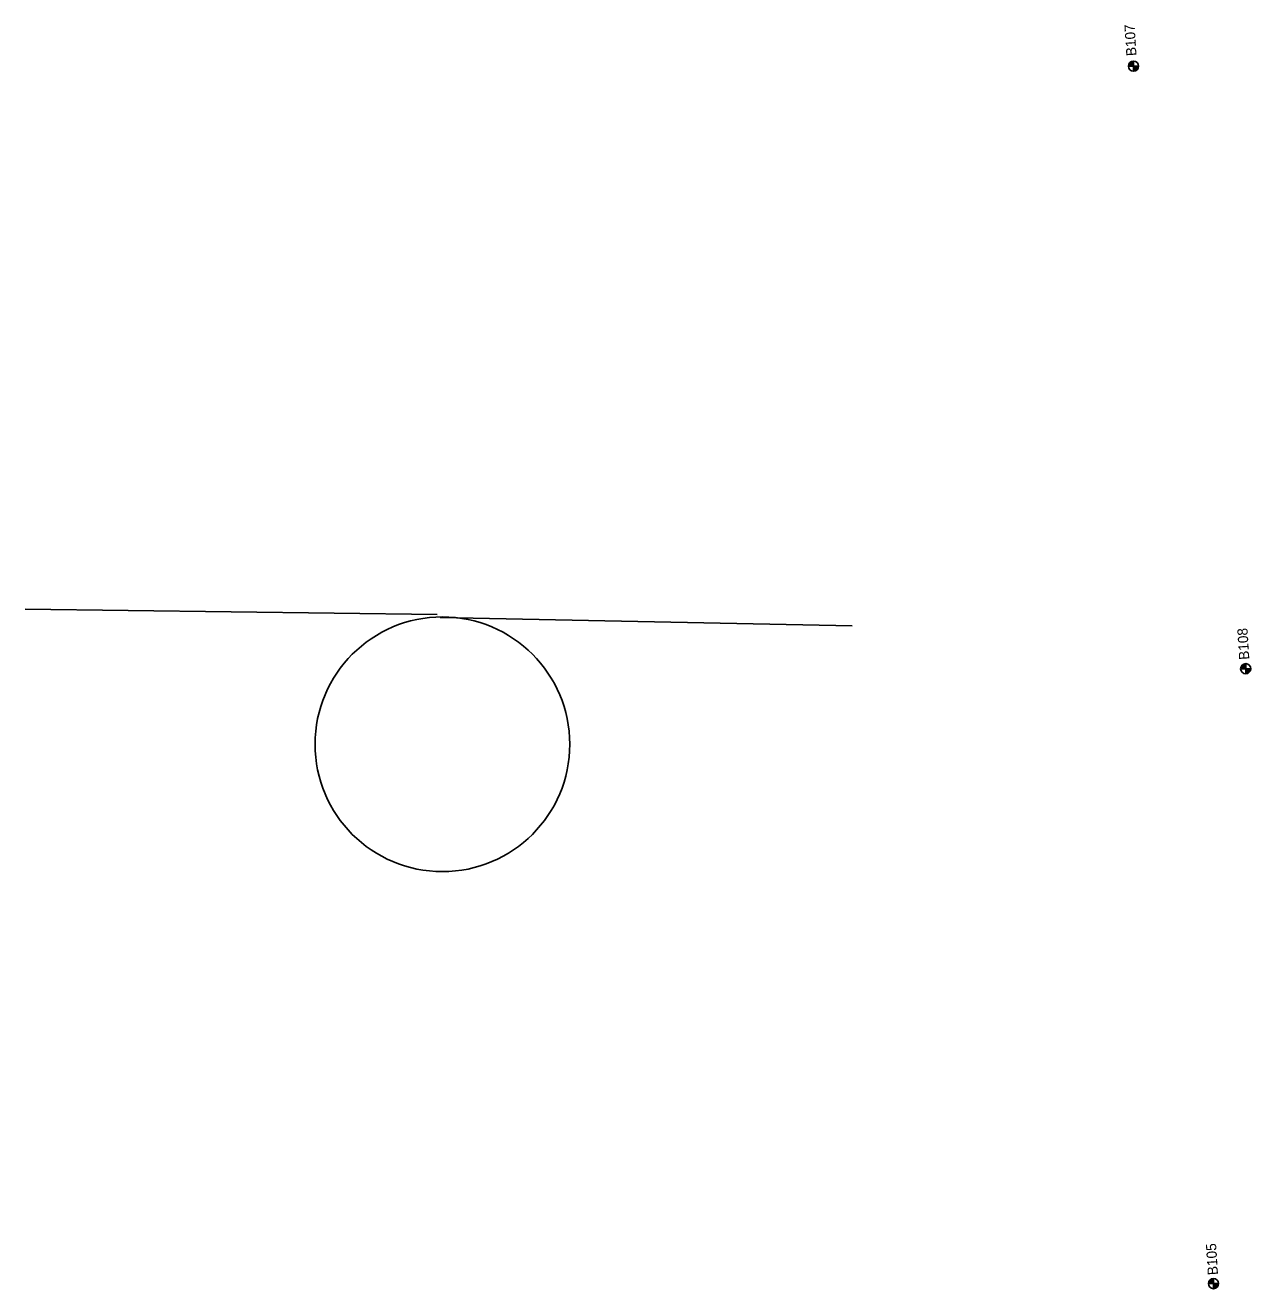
# Model space of a CAD drawing. Extents: x 311409 to 379449, y 121539 to 224848.
# Drawn here: x 354353 to 355558, y 186593 to 187835 of the extents above; entities that cross this region are included whole.
import ezdxf

# ---------------------------------------------------------------- set-up
doc = ezdxf.new("R2010")
doc.units = 0
for name, color, linetype in [('E_SOIL_BORE1 [KAPUR_CADDS_LEVELS]', 7, 'Continuous'), ('P_MARK', 7, 'Continuous'), ('SIGNS-POLES', 7, 'Continuous')]:
    doc.layers.add(name, color=color, linetype=linetype)

msp = doc.modelspace()

# ---------------------------------------------------------------- linework, layer by layer
at = {"layer": 'P_MARK'}
for p, q in [((355442.9, 187799.5), (355442.9, 187789.5)), ((355437.9, 187794.5), (355447.9, 187794.5)), ((355553.2, 187207.1), (355553.2, 187197.1)), ((355548.2, 187202.1), (355558.2, 187202.1)), ((355516.5, 186597.6), (355526.5, 186597.6)), ((355521.5, 186602.6), (355521.5, 186592.6))]:
    msp.add_line(p, q, dxfattribs=at)
for centre in [(355442.9, 187794.5), (355553.2, 187202.1), (355521.5, 186597.6)]:
    msp.add_circle(centre, 5, dxfattribs=at)
for centre, radius, start, end in [((355442.9, 187794.5), 4.5, 89.9869, 179.9869), ((355442.9, 187794.5), 4, 89.9869, 179.9869), ((355442.9, 187794.5), 3.5, 89.9869, 179.9869), ((355442.9, 187794.5), 3, 89.9869, 179.9869), ((355442.9, 187794.5), 2.5, 89.9869, 179.9869), ((355442.9, 187794.5), 2, 89.9869, 179.9869), ((355442.9, 187794.5), 1.5, 89.9869, 179.9869), ((355442.9, 187794.5), 1, 89.9869, 179.9869), ((355442.9, 187794.5), 0.5, 89.9869, 179.9869), ((355442.9, 187794.5), 4.5, 269.9869, 359.9869), ((355442.9, 187794.5), 4, 269.9869, 359.9869), ((355442.9, 187794.5), 3.5, 269.9869, 359.9869), ((355442.9, 187794.5), 3, 269.9869, 359.9869), ((355442.9, 187794.5), 2.5, 269.9869, 359.9869), ((355442.9, 187794.5), 2, 269.9869, 359.9869), ((355442.9, 187794.5), 1.5, 269.9869, 359.9869), ((355442.9, 187794.5), 1, 269.9869, 359.9869), ((355442.9, 187794.5), 0.5, 269.9869, 359.9869), ((355553.2, 187202.1), 4.5, 89.9869, 179.9869), ((355553.2, 187202.1), 4, 89.9869, 179.9869), ((355553.2, 187202.1), 3.5, 89.9869, 179.9869), ((355553.2, 187202.1), 3, 89.9869, 179.9869), ((355553.2, 187202.1), 2.5, 89.9869, 179.9869), ((355553.2, 187202.1), 2, 89.9869, 179.9869), ((355553.2, 187202.1), 1.5, 89.9869, 179.9869), ((355553.2, 187202.1), 1, 89.9869, 179.9869), ((355553.2, 187202.1), 0.5, 89.9869, 179.9869), ((355553.2, 187202.1), 4.5, 269.9869, 359.9869), ((355553.2, 187202.1), 4, 269.9869, 359.9869), ((355553.2, 187202.1), 3.5, 269.9869, 359.9869), ((355553.2, 187202.1), 3, 269.9869, 359.9869), ((355553.2, 187202.1), 2.5, 269.9869, 359.9869), ((355553.2, 187202.1), 2, 269.9869, 359.9869), ((355553.2, 187202.1), 1.5, 269.9869, 359.9869), ((355553.2, 187202.1), 1, 269.9869, 359.9869), ((355553.2, 187202.1), 0.5, 269.9869, 359.9869), ((355521.5, 186597.6), 4.5, 89.9869, 179.9869), ((355521.5, 186597.6), 4, 89.9869, 179.9869), ((355521.5, 186597.6), 3.5, 89.9869, 179.9869), ((355521.5, 186597.6), 3, 89.9869, 179.9869), ((355521.5, 186597.6), 2.5, 89.9869, 179.9869), ((355521.5, 186597.6), 2, 89.9869, 179.9869), ((355521.5, 186597.6), 1.5, 89.9869, 179.9869), ((355521.5, 186597.6), 1, 89.9869, 179.9869), ((355521.5, 186597.6), 0.5, 89.9869, 179.9869), ((355521.5, 186597.6), 4.5, 269.9869, 359.9869), ((355521.5, 186597.6), 4, 269.9869, 359.9869), ((355521.5, 186597.6), 3.5, 269.9869, 359.9869), ((355521.5, 186597.6), 3, 269.9869, 359.9869), ((355521.5, 186597.6), 2.5, 269.9869, 359.9869), ((355521.5, 186597.6), 2, 269.9869, 359.9869), ((355521.5, 186597.6), 1.5, 269.9869, 359.9869), ((355521.5, 186597.6), 1, 269.9869, 359.9869), ((355521.5, 186597.6), 0.5, 269.9869, 359.9869)]:
    msp.add_arc(centre, radius, start, end, dxfattribs=at)
at = {"layer": 'SIGNS-POLES'}
for p, q in [((354353.5, 187260.6), (354758.5, 187255.4)), ((354761.4, 187252.3), (355166.3, 187244.2))]:
    msp.add_line(p, q, dxfattribs=at)
msp.add_circle((354763.5, 187127.8), 125.2, dxfattribs=at)

# ---------------------------------------------------------------- texts
at = {"layer": 'E_SOIL_BORE1 [KAPUR_CADDS_LEVELS]'}
for s, p in [('B107', (355445.9, 187804.7)), ('B108', (355556.8, 187211.2)), ('B105', (355526, 186606.3))]:
    msp.add_text(s, height=10, rotation=93.5868, dxfattribs=at).set_placement(p)

doc.saveas('drawing.dxf')
